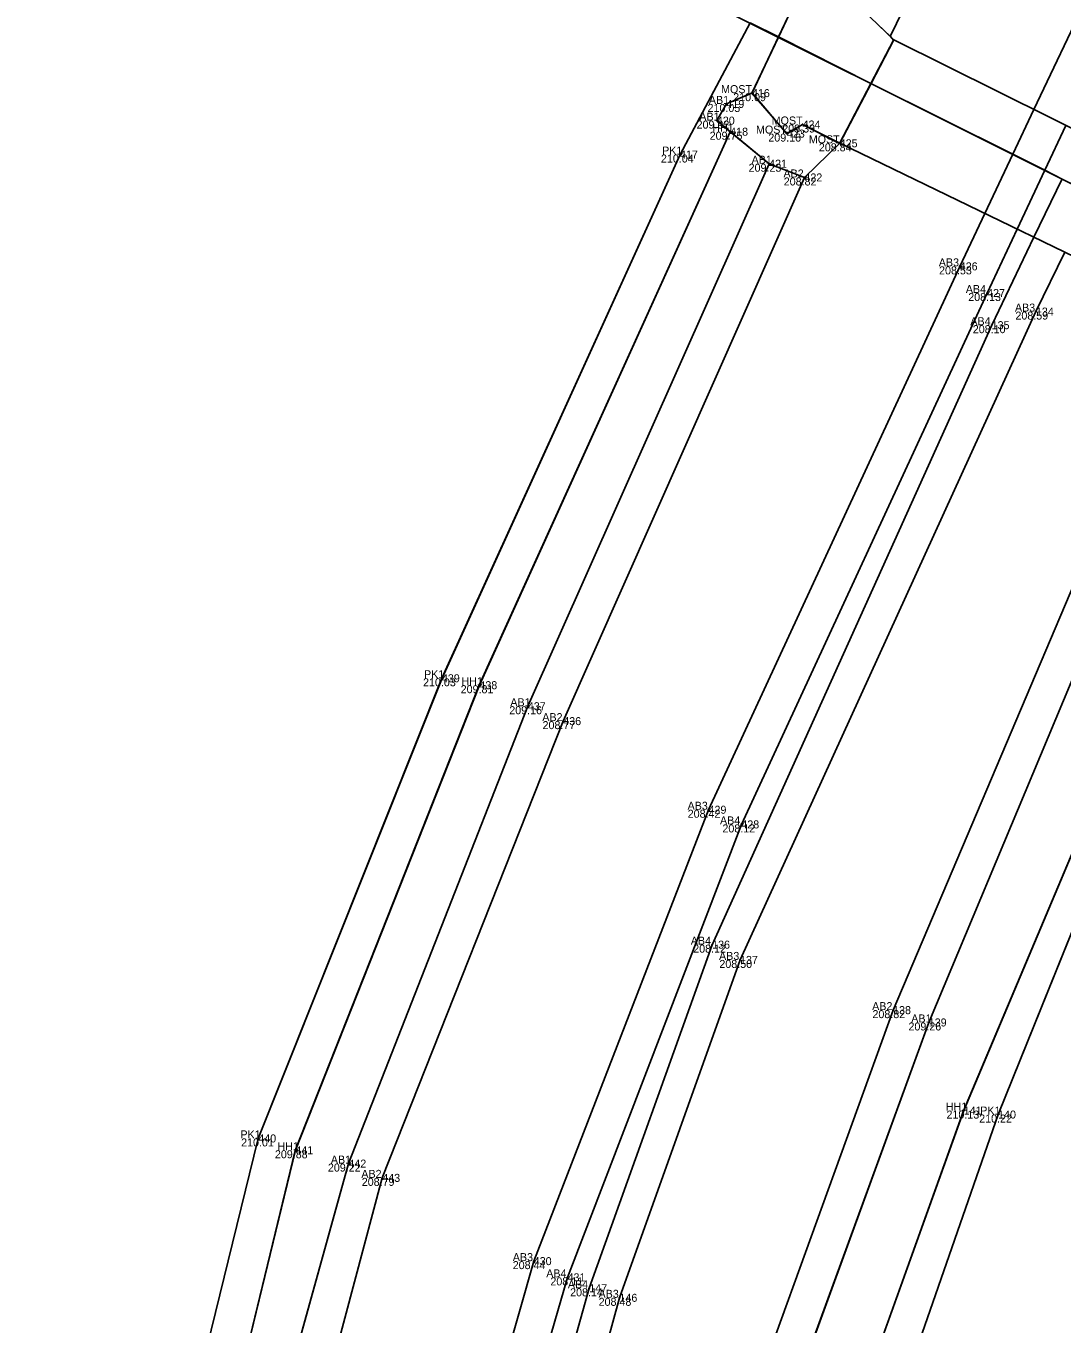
# Model space of a CAD drawing. Extents: x -262982 to -262706, y -1238714 to -1237093.
# Drawn here: x -262813.64 to -262787.74, y -1237705.27 to -1237672.82 of the extents above; entities that cross this region are included whole.
import ezdxf

# ---------------------------------------------------------------- set-up
doc = ezdxf.new("R2010")
doc.units = 0
for name, color, linetype in [('01_Hrana_betónu', 7, 'Continuous'), ('02_Oplotenie', 7, 'Continuous'), ('04_Most', 7, 'Continuous'), ('05_Hrana_terénu', 7, 'Continuous'), ('07_Iné', 7, 'Continuous'), ('10', 7, 'Continuous'), ('Groma (21)', 7, 'Continuous'), ('Groma (22)', 7, 'Continuous'), ('Groma (23)', 7, 'Continuous'), ('Groma (24)', 7, 'Continuous'), ('U004_Betónové_panely', 7, 'Continuous'), ('U004_Betóny_prídavné', 7, 'Continuous'), ('U004_Ostatné_plochy', 7, 'Continuous'), ('U004_Zeleň_mimo', 7, 'Continuous'), ('U004_Zeleň_vnútro', 7, 'Continuous'), ('U004_Zeleň_zatrávňovač', 7, 'Continuous'), ('U005_Betónové_panely', 7, 'Continuous'), ('U005_Ostatné_plochy', 7, 'Continuous'), ('U005_Zeleň_vnútro', 7, 'Continuous')]:
    doc.layers.add(name, color=color, linetype=linetype)

msp = doc.modelspace()

# ---------------------------------------------------------------- linework, layer by layer
at = {"layer": '01_Hrana_betónu'}
for p, q in [((-262791.945, -1237673.175), (-262792.515, -1237674.262)), ((-262792.515, -1237674.262), (-262793.299, -1237675.758))]:
    msp.add_line(p, q, dxfattribs=at)
for points in [[(-262788.441, -1237674.914), (-262786.102, -1237669.974), (-262779.96, -1237657.146), (-262772.255, -1237640.671), (-262762.405, -1237620.082), (-262753.353, -1237601.237), (-262748.855, -1237590.92), (-262745.54, -1237582.117), (-262743.431, -1237573.688), (-262742.016, -1237564.7), (-262741.168, -1237556.501), (-262740.979, -1237546.892), (-262740.851, -1237524.752), (-262740.671, -1237500.08), (-262740.394, -1237479.483), (-262740.216, -1237458.955), (-262740.117, -1237423.647), (-262740.094, -1237401.75), (-262740.13, -1237377.708), (-262740.243, -1237355.929), (-262740.317, -1237332.345), (-262740.44, -1237318.894), (-262740.323, -1237312.076)], [(-262744.671, -1237314.693), (-262744.322, -1237332.28), (-262744.032, -1237356.103), (-262743.621, -1237377.876), (-262743.427, -1237401.834), (-262743.334, -1237423.507), (-262743.665, -1237455.163), (-262743.89, -1237458.66), (-262743.816, -1237479.543), (-262744.125, -1237500.374), (-262744.256, -1237524.891), (-262744.407, -1237545.149), (-262744.747, -1237556.085), (-262745.544, -1237564.593), (-262746.648, -1237572.023), (-262748.879, -1237581.03), (-262752.099, -1237589.665), (-262756.673, -1237599.828), (-262765.314, -1237617.226), (-262775.804, -1237639.013), (-262783.576, -1237655.372), (-262792.033, -1237673.09)], [(-262788.971, -1237676.033), (-262788.441, -1237674.914)], [(-262787.643, -1237675.31), (-262788.171, -1237676.433)], [(-262789.671, -1237677.512), (-262788.971, -1237676.033)], [(-262833.49, -1237932.513), (-262832.358, -1237924.572), (-262831.993, -1237918.626), (-262831.904, -1237915.074), (-262831.439, -1237906.309), (-262830.324, -1237884.482), (-262828.859, -1237869.656), (-262826.973, -1237856.487), (-262824.752, -1237845.872), (-262820.768, -1237827.409), (-262815.971, -1237805.011), (-262811.874, -1237785.528), (-262810.073, -1237767.205), (-262809.465, -1237744.209), (-262809.348, -1237719.32), (-262807.762, -1237709.127), (-262805.583, -1237701.261), (-262801.096, -1237689.829), (-262795.064, -1237676.268)], [(-262794.181, -1237676.612), (-262800.21, -1237690.201), (-262804.735, -1237701.618), (-262806.814, -1237709.415), (-262808.46, -1237719.391), (-262808.589, -1237744.23), (-262809.169, -1237767.262), (-262810.977, -1237785.858), (-262815.119, -1237805.286), (-262819.878, -1237827.449), (-262823.898, -1237846.237), (-262826.14, -1237856.747), (-262827.996, -1237869.725), (-262829.453, -1237884.611), (-262830.572, -1237906.318), (-262830.909, -1237915.064), (-262831.044, -1237918.638), (-262831.379, -1237924.623), (-262832.499, -1237932.636), (-262832.416, -1237932.646)], [(-262788.171, -1237676.433), (-262788.862, -1237677.903)], [(-262787.74, -1237676.649), (-262788.441, -1237678.106)], [(-262828.366, -1237932.946), (-262828.106, -1237929.217), (-262827.649, -1237919.578), (-262827.369, -1237915.073), (-262826.968, -1237906.664), (-262825.835, -1237884.909), (-262824.318, -1237870.338), (-262822.252, -1237856.88), (-262820.394, -1237847.242), (-262816.344, -1237828.005), (-262811.527, -1237806.128), (-262807.485, -1237786.652), (-262805.817, -1237767.526), (-262804.904, -1237743.876), (-262804.544, -1237721.54), (-262802.773, -1237710.111), (-262800.948, -1237703.699), (-262796.578, -1237692.416), (-262790.297, -1237678.834), (-262789.671, -1237677.512)], [(-262788.862, -1237677.903), (-262789.612, -1237679.5), (-262795.758, -1237692.783), (-262800.102, -1237704.105), (-262801.904, -1237710.319), (-262803.638, -1237721.631), (-262804.041, -1237743.855), (-262804.886, -1237767.666), (-262806.567, -1237786.84), (-262810.653, -1237806.707), (-262815.575, -1237828.361), (-262819.614, -1237847.41), (-262821.404, -1237856.927), (-262823.638, -1237870.532), (-262825.083, -1237884.947), (-262826.299, -1237906.725), (-262827.242, -1237929.453), (-262827.527, -1237933.008)], [(-262788.441, -1237678.106), (-262789.499, -1237680.304), (-262796.488, -1237695.789), (-262799.561, -1237704.378), (-262801.599, -1237711.648), (-262803.17, -1237722.277), (-262803.523, -1237744.912), (-262804.331, -1237767.555), (-262806.033, -1237786.907), (-262810.428, -1237808.027), (-262815.321, -1237829.941), (-262818.5, -1237845.545), (-262820.865, -1237857.635), (-262822.962, -1237871.266), (-262824.386, -1237885.795), (-262825.49, -1237906.658), (-262826.835, -1237930.337), (-262826.931, -1237933.053)], [(-262825.987, -1237933.123), (-262825.899, -1237930.36), (-262825.137, -1237919.703), (-262824.89, -1237915.193), (-262824.65, -1237906.715), (-262823.596, -1237885.855), (-262822.137, -1237871.403), (-262820.061, -1237857.781), (-262817.692, -1237845.812), (-262814.459, -1237830.149), (-262809.645, -1237808.205), (-262805.191, -1237787.117), (-262803.484, -1237767.641), (-262802.568, -1237744.998), (-262802.266, -1237722.317), (-262800.862, -1237712.121), (-262798.805, -1237704.616), (-262795.791, -1237696.17), (-262788.393, -1237679.964), (-262787.674, -1237678.477)], [(-262783.803, -1237680.361), (-262791.072, -1237697.733), (-262794.156, -1237706.196), (-262796.111, -1237713.494), (-262797.353, -1237722.795), (-262798.006, -1237745.028), (-262798.995, -1237767.834), (-262800.837, -1237788.066), (-262805.174, -1237808.895), (-262810.048, -1237831.05), (-262813.207, -1237846.368), (-262815.438, -1237858.025), (-262817.519, -1237871.503), (-262819.01, -1237885.889), (-262819.761, -1237906.843), (-262819.991, -1237915.564)], [(-262820.488, -1237916.085), (-262820.893, -1237915.574), (-262820.599, -1237906.725), (-262819.894, -1237885.916), (-262818.364, -1237871.361), (-262816.365, -1237858.042), (-262814.122, -1237846.343), (-262810.891, -1237830.85), (-262806.137, -1237808.69), (-262801.736, -1237787.923), (-262799.952, -1237767.772), (-262798.979, -1237744.912), (-262798.159, -1237722.635), (-262796.927, -1237713.21), (-262795.035, -1237705.927), (-262791.963, -1237697.425), (-262785.076, -1237681.215)]]:
    msp.add_lwpolyline(points, dxfattribs=at)
at = {"layer": '02_Oplotenie'}
for points in [[(-262834.343, -1237921.203), (-262834.024, -1237915.302), (-262833.812, -1237906.279), (-262832.732, -1237884.616), (-262831.151, -1237869.343), (-262829.251, -1237856.325), (-262826.951, -1237845.31), (-262823.094, -1237827.731), (-262817.951, -1237804.339), (-262814.023, -1237784.135), (-262812.336, -1237767.05), (-262811.754, -1237744.594), (-262811.555, -1237719.093), (-262809.863, -1237708.888), (-262807.835, -1237700.632), (-262803.244, -1237689.13), (-262797.291, -1237676.038)], [(-262782.476, -1237683.046), (-262789.338, -1237700.035), (-262791.92, -1237707.468), (-262793.68, -1237714.792), (-262794.853, -1237723.195), (-262795.698, -1237745.299), (-262796.564, -1237768.081), (-262798.719, -1237788.188), (-262802.852, -1237809.448), (-262807.527, -1237831.589), (-262810.764, -1237846.834), (-262812.842, -1237857.763), (-262814.888, -1237871.127), (-262816.319, -1237886.182), (-262816.945, -1237895.233), (-262817.687, -1237906.993), (-262818.366, -1237915.571), (-262818.764, -1237925.136)]]:
    msp.add_lwpolyline(points, dxfattribs=at)
at = {"layer": '04_Most'}
for points in [[(-262794.832, -1237673.105), (-262794.423, -1237672.239), (-262794.016, -1237671.765), (-262792.919, -1237672.236), (-262791.945, -1237673.175), (-262782.754, -1237677.736), (-262781.704, -1237678.283), (-262781.563, -1237678.037), (-262780.7, -1237678.426), (-262780.481, -1237679.127), (-262780.925, -1237680.054)], [(-262780.925, -1237680.054), (-262781.499, -1237681.254), (-262782.189, -1237681.436), (-262783, -1237681.174), (-262782.961, -1237680.851), (-262783.935, -1237680.285), (-262793.299, -1237675.758), (-262794.227, -1237675.288), (-262794.619, -1237675.515), (-262795.493, -1237674.504), (-262794.832, -1237673.105)]]:
    msp.add_lwpolyline(points, dxfattribs=at)
at = {"layer": '05_Hrana_terénu'}
for points in [[(-262796.037, -1237675.468), (-262802.307, -1237689.303), (-262806.908, -1237700.928), (-262808.861, -1237708.991), (-262810.491, -1237719.246), (-262810.648, -1237744.371), (-262811.212, -1237767.185), (-262812.78, -1237784.48), (-262817.048, -1237804.549), (-262821.958, -1237827.467), (-262825.893, -1237845.536), (-262828.436, -1237856.363), (-262830.087, -1237869.518), (-262831.495, -1237884.449), (-262832.703, -1237906.272), (-262832.889, -1237914.228), (-262832.974, -1237914.835)], [(-262819.123, -1237925.833), (-262819.193, -1237924.361), (-262818.874, -1237915.472), (-262818.289, -1237906.84), (-262817.033, -1237886.241), (-262815.506, -1237871.209), (-262813.693, -1237857.604), (-262811.493, -1237846.649), (-262808.389, -1237831.401), (-262803.328, -1237809.401), (-262799.108, -1237788.219), (-262797.264, -1237767.972), (-262796.32, -1237745.233), (-262795.609, -1237723.113), (-262794.587, -1237714.488), (-262792.775, -1237707.13), (-262790.198, -1237699.936), (-262783.238, -1237683.427), (-262781.933, -1237681.667), (-262781.499, -1237681.254)]]:
    msp.add_lwpolyline(points, dxfattribs=at)
at = {"layer": '07_Iné'}
msp.add_lwpolyline([(-262793.299, -1237675.758), (-262794.181, -1237676.612), (-262795.064, -1237676.268), (-262796.37, -1237675.191), (-262796.131, -1237674.774), (-262795.493, -1237674.504)], dxfattribs=at)
at = {"layer": '10'}
msp.add_lwpolyline([(-262813.033, -1237664.011), (-262780.925, -1237680.054), (-262777.93, -1237681.41), (-262750.961, -1237695.025)], dxfattribs=at)
at = {"layer": 'Groma (21)'}
for centre in [(-262796.131, -1237674.774), (-262795.493, -1237674.504), (-262796.37, -1237675.191), (-262794.227, -1237675.288), (-262796.037, -1237675.468), (-262794.619, -1237675.515), (-262793.299, -1237675.758), (-262797.291, -1237676.038), (-262795.064, -1237676.268), (-262794.181, -1237676.612), (-262790.297, -1237678.834), (-262789.612, -1237679.5), (-262788.393, -1237679.964), (-262789.499, -1237680.304), (-262803.244, -1237689.13), (-262802.307, -1237689.303), (-262801.096, -1237689.829), (-262800.21, -1237690.201), (-262796.578, -1237692.416), (-262795.758, -1237692.783), (-262796.488, -1237695.789), (-262795.791, -1237696.17), (-262791.963, -1237697.425), (-262791.072, -1237697.733), (-262790.198, -1237699.936), (-262789.338, -1237700.035), (-262807.835, -1237700.632), (-262806.908, -1237700.928), (-262805.583, -1237701.261), (-262804.735, -1237701.618), (-262800.948, -1237703.699), (-262800.102, -1237704.105), (-262799.561, -1237704.378), (-262798.805, -1237704.616)]:
    msp.add_circle(centre, 0.01, dxfattribs=at)
at = {"layer": 'U004_Betónové_panely'}
msp.add_lwpolyline([(-262809.47, -1237744.21), (-262809.35, -1237719.32), (-262807.76, -1237709.13), (-262805.58, -1237701.26), (-262801.1, -1237689.83), (-262795.06, -1237676.27), (-262794.18, -1237676.61), (-262793.3, -1237675.76), (-262792.52, -1237674.26), (-262788.97, -1237676.03), (-262788.17, -1237676.43), (-262787.74, -1237676.65), (-262786.97, -1237677.03), (-262783.28, -1237678.88), (-262783.94, -1237680.28), (-262783.8, -1237680.36), (-262791.07, -1237697.73), (-262794.16, -1237706.2), (-262796.11, -1237713.49), (-262797.35, -1237722.8), (-262798.01, -1237745.03)], dxfattribs=at)
at = {"layer": 'U004_Betóny_prídavné'}
msp.add_lwpolyline([(-262796.37, -1237675.19), (-262796.13, -1237674.77), (-262795.49, -1237674.5), (-262794.62, -1237675.52), (-262794.23, -1237675.29), (-262793.3, -1237675.76), (-262794.18, -1237676.61), (-262795.06, -1237676.27)], close=True, dxfattribs=at)
at = {"layer": 'U004_Ostatné_plochy'}
msp.add_lwpolyline([(-262792.52, -1237674.26), (-262793.3, -1237675.76), (-262794.23, -1237675.29), (-262794.62, -1237675.52), (-262795.49, -1237674.5), (-262794.83, -1237673.1)], close=True, dxfattribs=at)
at = {"layer": 'U004_Zeleň_mimo'}
for points in [[(-262795.54, -1237672.75), (-262797.29, -1237676.04), (-262803.24, -1237689.13), (-262807.84, -1237700.63), (-262809.86, -1237708.89), (-262811.56, -1237719.09), (-262811.75, -1237744.59), (-262812.34, -1237767.05), (-262814.02, -1237784.14), (-262817.95, -1237804.34), (-262823.09, -1237827.73)], [(-262802.85, -1237809.45), (-262798.72, -1237788.19), (-262796.56, -1237768.08), (-262795.7, -1237745.3), (-262794.85, -1237723.2), (-262793.68, -1237714.79), (-262791.92, -1237707.47), (-262789.34, -1237700.03), (-262782.48, -1237683.05), (-262781.5, -1237681.25), (-262780.92, -1237680.05), (-262777.93, -1237681.41), (-262780.53, -1237687.57), (-262782.28, -1237691.67), (-262786.62, -1237706.53), (-262791.65, -1237746.49), (-262793.97, -1237766.45), (-262796.15, -1237782.82), (-262801.03, -1237810.71)]]:
    msp.add_lwpolyline(points, dxfattribs=at)
at = {"layer": 'U004_Zeleň_vnútro'}
for points in [[(-262811.75, -1237744.59), (-262811.56, -1237719.09), (-262809.86, -1237708.89), (-262807.84, -1237700.63), (-262803.24, -1237689.13), (-262797.29, -1237676.04), (-262795.54, -1237672.75), (-262794.83, -1237673.1), (-262795.49, -1237674.5), (-262796.13, -1237674.77), (-262796.37, -1237675.19), (-262796.04, -1237675.47), (-262802.31, -1237689.3), (-262806.91, -1237700.93), (-262808.86, -1237708.99), (-262810.49, -1237719.25), (-262810.65, -1237744.37)], [(-262803.33, -1237809.4), (-262799.11, -1237788.22), (-262797.26, -1237767.97), (-262796.32, -1237745.23), (-262795.61, -1237723.11), (-262794.59, -1237714.49), (-262792.78, -1237707.13), (-262790.2, -1237699.94), (-262783.24, -1237683.43), (-262782.19, -1237681.44), (-262781.5, -1237681.25), (-262782.48, -1237683.05), (-262789.34, -1237700.03), (-262791.92, -1237707.47), (-262793.68, -1237714.79), (-262794.85, -1237723.2), (-262795.7, -1237745.3), (-262796.56, -1237768.08), (-262798.72, -1237788.19), (-262802.85, -1237809.45)]]:
    msp.add_lwpolyline(points, dxfattribs=at)
at = {"layer": 'U004_Zeleň_zatrávňovač'}
for points in [[(-262821.96, -1237827.47), (-262817.05, -1237804.55), (-262812.78, -1237784.48), (-262811.21, -1237767.19), (-262810.65, -1237744.37), (-262810.49, -1237719.25), (-262808.86, -1237708.99), (-262806.91, -1237700.93), (-262802.31, -1237689.3), (-262796.04, -1237675.47), (-262795.06, -1237676.27), (-262801.1, -1237689.83), (-262805.58, -1237701.26), (-262807.76, -1237709.13), (-262809.35, -1237719.32), (-262809.47, -1237744.21), (-262810.07, -1237767.21), (-262811.87, -1237785.53), (-262815.97, -1237805.01)], [(-262805.17, -1237808.9), (-262800.84, -1237788.07), (-262799, -1237767.83), (-262798.01, -1237745.03), (-262797.35, -1237722.8), (-262796.11, -1237713.49), (-262794.16, -1237706.2), (-262791.07, -1237697.73), (-262783.8, -1237680.36), (-262782.96, -1237680.85), (-262783, -1237681.17), (-262782.19, -1237681.44), (-262783.24, -1237683.43), (-262790.2, -1237699.94), (-262792.78, -1237707.13), (-262794.59, -1237714.49), (-262795.61, -1237723.11), (-262796.32, -1237745.23), (-262797.26, -1237767.97), (-262799.11, -1237788.22), (-262803.33, -1237809.4)]]:
    msp.add_lwpolyline(points, dxfattribs=at)
at = {"layer": 'U005_Betónové_panely'}
msp.add_lwpolyline([(-262773.68, -1237660.32), (-262779.99, -1237673.1), (-262781.45, -1237675.8), (-262782.33, -1237677.96), (-262782.75, -1237677.74), (-262783.28, -1237678.88), (-262786.97, -1237677.03), (-262787.74, -1237676.65), (-262788.17, -1237676.43), (-262788.97, -1237676.03), (-262792.52, -1237674.26), (-262791.95, -1237673.18), (-262792.03, -1237673.09), (-262792.68, -1237672.47)], dxfattribs=at)
at = {"layer": 'U005_Ostatné_plochy'}
msp.add_lwpolyline([(-262792.52, -1237674.26), (-262794.83, -1237673.1), (-262794.42, -1237672.24), (-262794.02, -1237671.77), (-262792.92, -1237672.24), (-262792.68, -1237672.47), (-262792.03, -1237673.09), (-262791.95, -1237673.18)], close=True, dxfattribs=at)
at = {"layer": 'U005_Zeleň_vnútro'}
msp.add_lwpolyline([(-262794.42, -1237672.24), (-262794.83, -1237673.1), (-262795.54, -1237672.75)], dxfattribs=at)

# ---------------------------------------------------------------- texts
at = {"layer": 'Groma (22)'}
for s, p in [('416', (-262795.493, -1237674.604)), ('419', (-262796.131, -1237674.874)), ('420', (-262796.37, -1237675.291)), ('418', (-262796.037, -1237675.568)), ('423', (-262794.619, -1237675.615)), ('424', (-262794.227, -1237675.388)), ('425', (-262793.299, -1237675.858)), ('417', (-262797.291, -1237676.138)), ('421', (-262795.064, -1237676.368)), ('422', (-262794.181, -1237676.712)), ('426', (-262790.297, -1237678.934)), ('427', (-262789.612, -1237679.6)), ('134', (-262788.393, -1237680.064)), ('135', (-262789.499, -1237680.404)), ('439', (-262803.244, -1237689.23)), ('438', (-262802.307, -1237689.403)), ('437', (-262801.096, -1237689.929)), ('436', (-262800.21, -1237690.301)), ('429', (-262796.578, -1237692.516)), ('428', (-262795.758, -1237692.883)), ('136', (-262796.488, -1237695.889)), ('137', (-262795.791, -1237696.27)), ('138', (-262791.963, -1237697.525)), ('139', (-262791.072, -1237697.833)), ('141', (-262790.198, -1237700.036)), ('140', (-262789.338, -1237700.135)), ('440', (-262807.835, -1237700.732)), ('441', (-262806.908, -1237701.028)), ('442', (-262805.583, -1237701.361)), ('443', (-262804.735, -1237701.718)), ('430', (-262800.948, -1237703.799)), ('431', (-262800.102, -1237704.205)), ('147', (-262799.561, -1237704.478)), ('146', (-262798.805, -1237704.716))]:
    msp.add_text(s, height=0.2, dxfattribs=at).set_placement(p)
at = {"layer": 'Groma (23)'}
for s, p in [('210.05', (-262796.603, -1237674.974)), ('210.09', (-262795.961, -1237674.704)), ('209.92', (-262796.877, -1237675.391)), ('209.39', (-262794.734, -1237675.488)), ('209.75', (-262796.55, -1237675.668)), ('209.16', (-262795.083, -1237675.715)), ('208.84', (-262793.82, -1237675.958)), ('210.04', (-262797.768, -1237676.238)), ('209.23', (-262795.576, -1237676.468)), ('208.82', (-262794.698, -1237676.812)), ('208.53', (-262790.814, -1237679.034)), ('208.13', (-262790.085, -1237679.7)), ('208.59', (-262788.905, -1237680.164)), ('208.10', (-262789.971, -1237680.504)), ('210.03', (-262803.716, -1237689.33)), ('209.81', (-262802.775, -1237689.503)), ('209.16', (-262801.56, -1237690.029)), ('208.77', (-262800.728, -1237690.401)), ('208.42', (-262797.099, -1237692.616)), ('208.12', (-262796.231, -1237692.983)), ('208.12', (-262796.961, -1237695.989)), ('208.50', (-262796.307, -1237696.37)), ('208.82', (-262792.48, -1237697.625)), ('209.26', (-262791.579, -1237697.933)), ('210.13', (-262790.628, -1237700.136)), ('210.22', (-262789.811, -1237700.235)), ('210.01', (-262808.264, -1237700.832)), ('209.88', (-262807.42, -1237701.128)), ('209.22', (-262806.095, -1237701.461)), ('208.79', (-262805.248, -1237701.818)), ('208.44', (-262801.474, -1237703.899)), ('208.11', (-262800.532, -1237704.305)), ('208.14', (-262800.039, -1237704.578)), ('208.48', (-262799.326, -1237704.816))]:
    msp.add_text(s, height=0.2, dxfattribs=at).set_placement(p)
at = {"layer": 'Groma (24)'}
for s, p in [('MOST', (-262796.265, -1237674.504)), ('AB1', (-262796.569, -1237674.774)), ('AB1', (-262796.808, -1237675.191)), ('MOST', (-262794.999, -1237675.288)), ('HH1', (-262796.484, -1237675.468)), ('MOST', (-262795.391, -1237675.515)), ('MOST', (-262794.071, -1237675.758)), ('PK1', (-262797.738, -1237676.038)), ('AB1', (-262795.502, -1237676.268)), ('AB2', (-262794.705, -1237676.612)), ('AB3', (-262790.821, -1237678.834)), ('AB4', (-262790.146, -1237679.5)), ('AB3', (-262788.917, -1237679.964)), ('AB4', (-262790.033, -1237680.304)), ('PK1', (-262803.691, -1237689.13)), ('HH1', (-262802.754, -1237689.303)), ('AB1', (-262801.534, -1237689.829)), ('AB2', (-262800.734, -1237690.201)), ('AB3', (-262797.102, -1237692.416)), ('AB4', (-262796.292, -1237692.783)), ('AB4', (-262797.022, -1237695.789)), ('AB3', (-262796.315, -1237696.17)), ('AB2', (-262792.487, -1237697.425)), ('AB1', (-262791.51, -1237697.733)), ('HH1', (-262790.645, -1237699.936)), ('PK1', (-262789.785, -1237700.035)), ('PK1', (-262808.282, -1237700.632)), ('HH1', (-262807.355, -1237700.928)), ('AB1', (-262806.021, -1237701.261)), ('AB2', (-262805.259, -1237701.618)), ('AB3', (-262801.472, -1237703.699)), ('AB4', (-262800.636, -1237704.105)), ('AB4', (-262800.095, -1237704.378)), ('AB3', (-262799.329, -1237704.616))]:
    msp.add_text(s, height=0.2, dxfattribs=at).set_placement(p)

doc.saveas('drawing.dxf')
